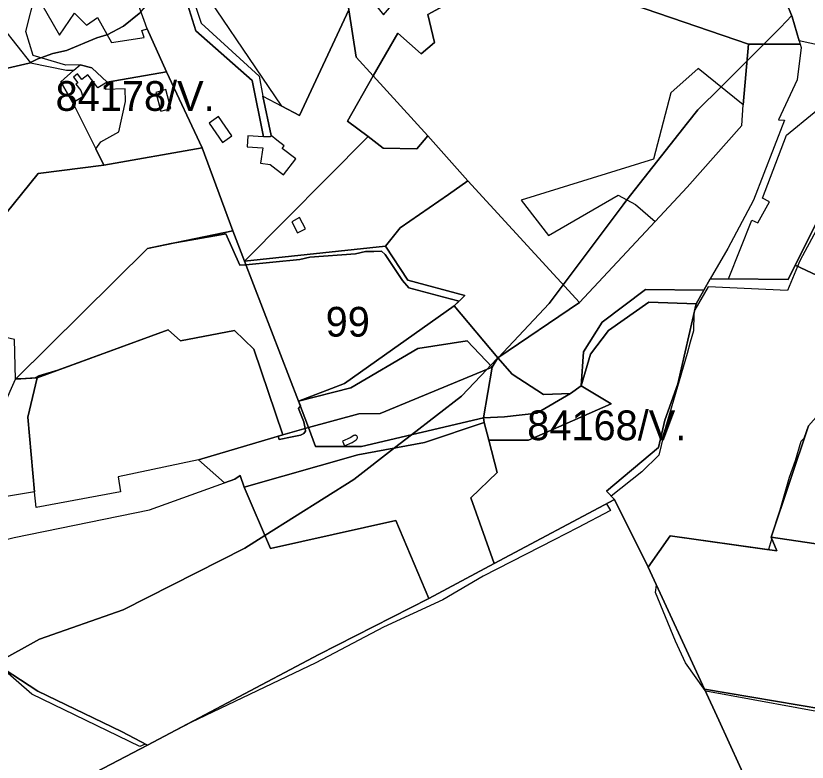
# Model space of a CAD drawing. Extents: x -477304 to -465429, y -1159113 to -1149210.
# Drawn here: x -472989.3 to -472589.9, y -1156050.1 to -1155673.5 of the extents above; entities that cross this region are included whole.
import ezdxf

# ---------------------------------------------------------------- set-up
doc = ezdxf.new("R2010")
doc.units = 0
for name, color, linetype in [('BPEJ_s', 7, 'Continuous'), ('orna_s', 7, 'Continuous'), ('PUPFL_s', 7, 'Continuous'), ('trav_porost_s', 7, 'Continuous')]:
    doc.layers.add(name, color=color, linetype=linetype)

msp = doc.modelspace()

# ---------------------------------------------------------------- linework, layer by layer
at = {"layer": 'BPEJ_s'}
for points in [[(-472922.7, -1155667.34), (-472926.21, -1155671.37), (-472927.05, -1155672.33), (-472934.92, -1155678.7), (-472943.3, -1155683.11), (-472943.42, -1155683.17), (-472948.52, -1155684.66), (-472963.83, -1155691.04), (-472970.64, -1155692.53), (-472976.73, -1155694.73), (-472977.77, -1155695.1), (-472978.3, -1155695.29), (-472982, -1155697.14), (-472982.55, -1155697.42), (-472998.16, -1155700.91)], [(-472999.06, -1156000), (-472977.35, -1155987.95), (-472935.14, -1155973.23), (-472873.79, -1155942.06), (-472863.6, -1155935.65), (-472818.82, -1155907.46), (-472798.19, -1155891.57), (-472789.56, -1155884.92), (-472764.35, -1155865.5), (-472751.49, -1155851.86), (-472749.73, -1155849.99), (-472746.1, -1155846.14), (-472746.04, -1155846.07), (-472745.98, -1155846.01), (-472720.17, -1155818.63), (-472713.13, -1155809.22), (-472682.88, -1155768.82), (-472680.95, -1155766.37), (-472650.31, -1155727.58), (-472645.08, -1155720.96), (-472633.43, -1155709.38), (-472620.23, -1155696.26), (-472611.73, -1155687.81), (-472603.37, -1155679.49), (-472597.67, -1155673.42)], [(-472597.67, -1155673.42), (-472603.37, -1155679.49), (-472611.73, -1155687.81), (-472620.23, -1155696.26), (-472633.43, -1155709.38), (-472645.08, -1155720.96), (-472650.31, -1155727.58), (-472680.95, -1155766.37), (-472682.88, -1155768.82), (-472713.13, -1155809.22), (-472720.17, -1155818.63), (-472745.98, -1155846.01), (-472746.04, -1155846.07), (-472746.1, -1155846.14), (-472749.73, -1155849.99), (-472751.49, -1155851.86), (-472764.35, -1155865.5), (-472789.56, -1155884.92), (-472798.19, -1155891.57), (-472818.82, -1155907.46), (-472863.6, -1155935.65), (-472873.79, -1155942.06), (-472935.14, -1155973.23), (-472977.35, -1155987.95), (-472999.06, -1156000)], [(-472998.16, -1155700.91), (-472982.55, -1155697.42), (-472982, -1155697.14), (-472978.3, -1155695.29), (-472977.77, -1155695.1), (-472976.73, -1155694.73), (-472970.64, -1155692.53), (-472963.83, -1155691.04), (-472948.52, -1155684.66), (-472943.42, -1155683.17), (-472943.3, -1155683.11), (-472934.92, -1155678.7), (-472927.05, -1155672.33)], [(-472585.41, -1155781.89), (-472593.44, -1155796.84), (-472594.07, -1155798.33), (-472594.75, -1155799.96), (-472599.87, -1155812.06), (-472639.86, -1155810.3), (-472646.67, -1155821.88), (-472647.11, -1155823.83), (-472647.28, -1155832.44), (-472648.94, -1155838.21), (-472650.59, -1155843.95), (-472661.52, -1155881.31), (-472664.83, -1155895.16), (-472673.42, -1155903.55), (-472688.8, -1155915.86), (-472687.19, -1155917.6), (-472691.17, -1155919.72), (-472689.22, -1155923.06), (-472705.8, -1155931.93), (-472717.7, -1155937.98), (-472753.4, -1155956.22), (-472773.89, -1155968.12), (-472803.73, -1155981.97), (-472837.9, -1156000), (-472901.01, -1156029.99), (-472922.96, -1156041.59), (-472924.1, -1156040.97), (-472926.8, -1156042.25), (-472981.23, -1156015.76), (-472997.16, -1156001.93)], [(-472585.41, -1155781.89), (-472593.44, -1155796.84), (-472594.07, -1155798.33), (-472594.75, -1155799.96), (-472599.87, -1155812.06), (-472639.86, -1155810.3), (-472646.67, -1155821.88), (-472647.11, -1155823.83), (-472647.28, -1155832.44), (-472648.94, -1155838.21), (-472650.59, -1155843.95)], [(-472650.59, -1155843.95), (-472661.52, -1155881.31), (-472664.83, -1155895.16), (-472673.42, -1155903.55), (-472688.8, -1155915.86), (-472687.19, -1155917.6), (-472691.17, -1155919.72), (-472689.22, -1155923.06), (-472705.8, -1155931.93), (-472717.7, -1155937.98), (-472753.4, -1155956.22), (-472773.89, -1155968.12), (-472803.73, -1155981.97), (-472837.9, -1156000), (-472901.01, -1156029.99), (-472922.96, -1156041.59), (-472924.1, -1156040.97), (-472926.8, -1156042.25), (-472981.23, -1156015.76), (-472997.16, -1156001.93)], [(-472571.21, -1156027.12), (-472641.15, -1156014.28), (-472641.35, -1156014.01), (-472651.43, -1156000), (-472656.44, -1155989.1), (-472666.48, -1155964.42), (-472665.94, -1155960.8), (-472670.13, -1155951.75), (-472659.11, -1155935.96), (-472609.16, -1155942.97), (-472609.23, -1155942.79), (-472609.29, -1155942.63), (-472607.77, -1155937.52), (-472608.16, -1155936.56), (-472603.52, -1155922.75), (-472598.9, -1155906.37), (-472595.84, -1155897.86), (-472592.95, -1155888.16), (-472591.41, -1155886.7), (-472589.29, -1155880.38)], [(-472571.21, -1156027.12), (-472641.15, -1156014.28), (-472641.35, -1156014.01), (-472651.43, -1156000), (-472656.44, -1155989.1), (-472666.48, -1155964.42), (-472665.94, -1155960.8), (-472670.13, -1155951.75), (-472659.11, -1155935.96), (-472609.16, -1155942.97), (-472609.23, -1155942.79), (-472609.29, -1155942.63), (-472607.77, -1155937.52), (-472608.16, -1155936.56), (-472603.52, -1155922.75), (-472598.9, -1155906.37), (-472595.84, -1155897.86), (-472592.95, -1155888.16), (-472591.41, -1155886.7), (-472589.29, -1155880.38)]]:
    msp.add_lwpolyline(points, dxfattribs=at)
for points in [[(-472883.38, -1155783.49), (-472876.34, -1155799.4), (-472873.26, -1155799.11), (-472846.03, -1155796.51), (-472840.93, -1155795.23), (-472817.96, -1155793.53), (-472812.86, -1155792.47), (-472808.73, -1155792.36), (-472804.78, -1155792.25), (-472802.87, -1155793.95), (-472794.15, -1155807.14), (-472790.96, -1155810.75), (-472773.31, -1155815.43), (-472765.65, -1155817.46), (-472768.13, -1155819.86), (-472823.5, -1155858.96), (-472846.71, -1155867.87), (-472845.74, -1155870.37), (-472846.67, -1155871.57), (-472843.91, -1155878.37), (-472843.3, -1155881.73), (-472843.06, -1155883.05), (-472843.91, -1155884.33), (-472845.61, -1155885.18), (-472849.89, -1155886), (-472856.42, -1155887.26), (-472856.97, -1155885.68), (-472854.55, -1155884.97), (-472869.3, -1155841.75), (-472879.05, -1155832.25), (-472906.29, -1155837.48), (-472912.41, -1155832.04), (-472968.11, -1155852.34), (-472977.66, -1155855.19), (-472979.6, -1155856.24), (-472986.85, -1155856.72), (-472989.11, -1155856.43), (-472922.84, -1155790.9), (-472910.99, -1155788.46), (-472886.01, -1155783.96)], [(-472883.38, -1155783.49), (-472886.01, -1155783.96), (-472910.99, -1155788.46), (-472922.84, -1155790.9), (-472989.11, -1155856.43), (-472986.85, -1155856.72), (-472979.6, -1155856.24), (-472977.66, -1155855.19), (-472968.11, -1155852.34), (-472912.41, -1155832.04), (-472906.29, -1155837.48), (-472879.05, -1155832.25), (-472869.3, -1155841.75), (-472854.55, -1155884.97), (-472856.97, -1155885.68), (-472856.42, -1155887.26), (-472849.89, -1155886), (-472845.61, -1155885.18), (-472843.91, -1155884.33), (-472843.06, -1155883.05), (-472843.3, -1155881.73), (-472843.91, -1155878.37), (-472846.67, -1155871.57), (-472845.74, -1155870.37), (-472846.71, -1155867.87), (-472823.5, -1155858.96), (-472768.13, -1155819.86), (-472765.65, -1155817.46), (-472773.31, -1155815.43), (-472790.96, -1155810.75), (-472794.15, -1155807.14), (-472802.87, -1155793.95), (-472804.78, -1155792.25), (-472808.73, -1155792.36), (-472812.86, -1155792.47), (-472817.96, -1155793.53), (-472840.93, -1155795.23), (-472846.03, -1155796.51), (-472873.26, -1155799.11), (-472876.34, -1155799.4)]]:
    msp.add_lwpolyline(points, close=True, dxfattribs=at)
at = {"layer": 'orna_s'}
msp.add_lwpolyline([(-472904.44, -1155646.21), (-472874.2, -1155639.71), (-472825.33, -1155645.43), (-472821.33, -1155670.54), (-472846.2, -1155723.83), (-472855.05, -1155719.18)], close=True, dxfattribs=at)
at = {"layer": 'PUPFL_s'}
for points in [[(-472572.16, -1155777.59), (-472514.27, -1155815.34), (-472498.14, -1155825.67), (-472490.85, -1155822.58), (-472477.53, -1155830.42), (-472448.56, -1155789.04), (-472474.55, -1155756.52), (-472484.66, -1155743.65), (-472534.93, -1155704.64), (-472531.73, -1155698.69), (-472519.37, -1155692.24), (-472415.14, -1155824.92), (-472416.46, -1155829.67), (-472432.07, -1155851.62), (-472438.54, -1155857.96), (-472472.35, -1155859.71), (-472574.19, -1155809.59), (-472596.01, -1155799.37), (-472572.9, -1155753.43), (-472551.81, -1155736.18)], [(-472841.55, -1155881.23), (-472854.55, -1155884.97), (-472869.3, -1155841.75), (-472879.05, -1155832.25), (-472906.29, -1155837.48), (-472912.41, -1155832.04), (-472978.64, -1155856.18), (-472989.58, -1155856.9), (-472922.84, -1155790.9), (-472879.9, -1155782.07), (-472873.94, -1155797.34), (-472846.71, -1155867.87)], [(-472873.94, -1155797.34), (-472802.83, -1155789.76), (-472791.56, -1155806.97), (-472762.68, -1155814.59), (-472768.13, -1155819.86), (-472823.5, -1155858.96), (-472846.71, -1155867.87)], [(-472661.79, -1155877.51), (-472655.14, -1155859.25), (-472645.98, -1155818.85), (-472642.13, -1155812), (-472638.84, -1155806.16), (-472629.58, -1155806.24), (-472599.61, -1155806.52), (-472596.01, -1155799.37), (-472574.19, -1155809.59), (-472472.35, -1155859.71), (-472488.97, -1155894.11), (-472503.35, -1155895.81), (-472532.79, -1155892.95), (-472559.66, -1155893.64), (-472569.59, -1155891.1), (-472584.19, -1155874.69), (-472589.29, -1155880.38), (-472608.16, -1155936.56), (-472605.33, -1155943.51), (-472659.11, -1155935.96), (-472670.13, -1155951.75), (-472687.19, -1155917.6), (-472691.18, -1155913.29), (-472664.95, -1155891.32)], [(-472742.74, -1155875.87), (-472753.29, -1155876.35), (-472748.95, -1155850.81), (-472746.05, -1155846.06), (-472738.91, -1155854.32), (-472723.07, -1155864.54), (-472709.44, -1155864.05), (-472726.33, -1155874.06)], [(-472748.95, -1155850.81), (-472753.29, -1155876.35), (-472814.81, -1155890.89), (-472838.13, -1155890.86), (-472841.55, -1155881.23), (-472816.2, -1155874.36), (-472805.5, -1155874.22)], [(-472704.05, -1155860.24), (-472688.81, -1155869.22), (-472730.61, -1155887.59), (-472750.54, -1155887.57), (-472752.92, -1155878.75), (-472753.29, -1155876.35), (-472742.74, -1155875.87), (-472726.33, -1155874.06), (-472709.44, -1155864.05)], [(-472841.55, -1155881.23), (-472838.13, -1155890.86), (-472814.81, -1155890.89), (-472753.29, -1155876.35), (-472752.92, -1155878.75), (-472783.15, -1155888.77), (-472816.72, -1155895.02), (-472874.07, -1155911.28), (-472876.19, -1155905.49), (-472878.88, -1155907.3), (-472884.02, -1155909.16), (-472897.09, -1155897.5), (-472854.55, -1155884.97)], [(-472818.77, -1155885.32), (-472820.65, -1155886.43), (-472824.44, -1155888.07), (-472823.42, -1155890.41), (-472819.64, -1155888.78), (-472817.49, -1155887.4), (-472817.37, -1155887.29), (-472817.18, -1155887.08), (-472817.04, -1155886.83), (-472816.96, -1155886.53), (-472816.95, -1155886.37), (-472816.98, -1155886.09), (-472817.1, -1155885.77), (-472817.29, -1155885.52), (-472817.53, -1155885.33), (-472817.78, -1155885.21), (-472817.97, -1155885.17), (-472818.25, -1155885.16), (-472818.53, -1155885.21)], [(-473111.65, -1156073.71), (-473056.5, -1156049.27), (-473048.89, -1156045.89), (-473050.49, -1156023.91), (-473057.72, -1156010.51), (-473038.71, -1156011.58), (-473037.79, -1155982.27), (-473034.32, -1155981.8), (-473010.5, -1156006.64), (-472999.71, -1156000.27), (-472978.22, -1156014.28), (-472935.93, -1156034.53), (-472922.96, -1156041.59), (-473045.7, -1156105.54), (-473097.04, -1156103.37), (-473101, -1156113.09), (-473145.64, -1156142.47), (-473152.6, -1156129.97), (-473153.83, -1156074.08), (-473144.15, -1156046.2), (-473122.88, -1156061.84), (-473122.25, -1156069.17)], [(-472634.3, -1156085.9), (-472613.74, -1156074.61), (-472634.46, -1156028.9), (-472641.69, -1156013.27), (-472582.01, -1156023.28), (-472562.66, -1156023.79), (-472541.93, -1156016.78), (-472537.65, -1156016.92), (-472541.68, -1156019.13), (-472538.91, -1156069.82), (-472596.62, -1156079.6)]]:
    msp.add_lwpolyline(points, close=True, dxfattribs=at)
msp.add_lwpolyline([(-473100.49, -1156468.81), (-473078.33, -1156321.91), (-473045.7, -1156105.54), (-472922.96, -1156041.59), (-472836.38, -1155995.84), (-472780.83, -1155967.48), (-472747.87, -1155949.92), (-472687.19, -1155917.6), (-472670.13, -1155951.75), (-472641.69, -1156013.27), (-472634.46, -1156028.9), (-472613.74, -1156074.61), (-472634.3, -1156085.9), (-472850.56, -1156204.67), (-472863.16, -1156211.61), (-472899.78, -1156412.46), (-472686.97, -1156467.54)], dxfattribs=at)
at = {"layer": 'trav_porost_s'}
for points in [[(-472825.33, -1155645.43), (-472816.82, -1155656.3), (-472803.73, -1155673.01), (-472788.76, -1155655.34), (-472782.65, -1155648.13), (-472797.55, -1155628.71), (-472825.33, -1155645.43), (-472834.02, -1155597.18), (-472718.7, -1155588.71), (-472701.9, -1155614.11), (-472701.84, -1155632.24), (-472739.24, -1155627.74), (-472738.35, -1155648.61), (-472727, -1155652.3), (-472740.79, -1155654.51), (-472740.31, -1155657.81), (-472765.97, -1155664.23), (-472781.32, -1155672.86), (-472778.1, -1155687.01), (-472784.81, -1155692.77), (-472796.52, -1155682.3), (-472809.03, -1155703.76), (-472817.54, -1155694.41), (-472821.33, -1155670.54)], [(-472938.48, -1155637.04), (-472939.51, -1155629.75), (-472916.76, -1155614.14), (-472914.52, -1155632.41), (-472904.62, -1155650.72), (-472895.84, -1155677.28), (-472866.51, -1155703.99), (-472864.63, -1155714.13), (-472860.5, -1155733.98), (-472860.99, -1155734.61), (-472864.32, -1155734.51), (-472870.03, -1155706.22), (-472898.52, -1155681.15), (-472907.7, -1155651.3), (-472920.94, -1155636.86)], [(-472672.2, -1155632.87), (-472629.35, -1155623.11), (-472617.53, -1155624.42), (-472597.43, -1155674), (-472593.93, -1155686.1), (-472593.45, -1155687.75), (-472619.47, -1155687.83), (-472671.7, -1155670), (-472727, -1155652.3), (-472738.35, -1155648.61), (-472739.24, -1155627.74), (-472701.84, -1155632.24)], [(-472685.36, -1155764.03), (-472676.59, -1155768.69), (-472666.59, -1155777.31), (-472704.85, -1155818.24), (-472761.29, -1155756.77), (-472781.48, -1155734.03), (-472809.03, -1155703.76), (-472796.52, -1155682.3), (-472784.81, -1155692.77), (-472778.1, -1155687.01), (-472781.32, -1155672.86), (-472765.97, -1155664.23), (-472740.31, -1155657.81), (-472740.79, -1155654.51), (-472727, -1155652.3), (-472671.7, -1155670), (-472619.47, -1155687.83), (-472622.25, -1155718.47), (-472644.89, -1155700.06), (-472658.74, -1155712.37), (-472667.58, -1155745.86), (-472734.29, -1155766.5), (-472720.46, -1155784.36)], [(-472959.66, -1155672.24), (-472953.72, -1155678.23), (-472948.17, -1155674.4), (-472941.08, -1155687.07), (-472924.64, -1155684.52), (-472925.74, -1155681.01), (-472923.11, -1155680.05), (-472913.24, -1155701.82), (-472943.29, -1155707.06), (-472951.01, -1155699.76), (-472956.94, -1155698.28), (-472964.13, -1155698.43), (-472980.61, -1155693.59), (-472984.29, -1155681.38), (-472979.36, -1155662.17), (-472967.33, -1155683.31)], [(-472998.55, -1155704.27), (-472995.67, -1155679.73), (-472981.91, -1155697.25), (-472963.84, -1155700.94), (-472960.02, -1155700.99), (-472966.66, -1155706.82), (-472960.52, -1155717.37), (-472949.03, -1155740.56), (-472944.94, -1155748.81), (-472978.04, -1155753.06), (-472998.57, -1155778.3), (-473002.71, -1155739.02), (-473042.47, -1155744.26), (-473043.29, -1155736.01), (-473043.13, -1155717.33), (-473006.44, -1155706.58)], [(-472622.99, -1155728.81), (-472622.25, -1155718.47), (-472619.47, -1155687.83), (-472593.45, -1155687.75), (-472592.97, -1155689.43), (-472595, -1155705.79), (-472604.46, -1155725.98), (-472601.32, -1155726.25), (-472617.01, -1155766.52), (-472629.97, -1155790.89), (-472638.84, -1155806.16), (-472642.13, -1155812), (-472671.49, -1155811.6), (-472693.44, -1155828.03), (-472702.86, -1155843.1), (-472704.05, -1155860.24), (-472709.44, -1155864.05), (-472723.07, -1155864.54), (-472738.91, -1155854.32), (-472746.05, -1155846.06), (-472704.85, -1155818.24), (-472666.59, -1155777.31), (-472650.57, -1155760.02)], [(-472950.53, -1155706.49), (-472952.99, -1155703.33), (-472955.99, -1155705.67), (-472958.18, -1155702.87), (-472960.23, -1155704.47), (-472958.05, -1155707.27), (-472959.07, -1155708.07), (-472956.61, -1155711.23), (-472955.55, -1155714.39), (-472960.52, -1155717.37), (-472966.66, -1155706.82), (-472960.02, -1155700.99), (-472956.94, -1155698.28), (-472951.01, -1155699.76), (-472943.29, -1155707.06), (-472947.93, -1155709.83)], [(-472946.51, -1155737.07), (-472937.33, -1155731.99), (-472934.01, -1155716.68), (-472934.22, -1155710.42), (-472944.02, -1155710.75), (-472943.29, -1155707.06), (-472913.24, -1155701.82), (-472895.22, -1155740.09), (-472944.94, -1155748.81), (-472949.03, -1155740.56)], [(-472809.03, -1155703.76), (-472781.48, -1155734.03), (-472786.97, -1155740.59), (-472804, -1155740.25), (-472811.58, -1155734.37), (-472821.93, -1155726.6)], [(-472911.03, -1155720.31), (-472913.56, -1155710.73), (-472918.75, -1155712.16), (-472916.14, -1155721.66)], [(-472885.03, -1155737.43), (-472880.24, -1155734.09), (-472887.03, -1155724.32), (-472891.83, -1155727.66)], [(-472802.83, -1155789.76), (-472873.94, -1155797.34), (-472811.58, -1155734.37), (-472804, -1155740.25), (-472786.97, -1155740.59), (-472781.48, -1155734.03), (-472761.29, -1155756.77), (-472770.95, -1155763.7), (-472795.33, -1155780.53)], [(-472998.57, -1155778.3), (-472978.04, -1155753.06), (-472944.94, -1155748.81), (-472895.22, -1155740.09), (-472879.9, -1155782.07), (-472922.84, -1155790.9), (-472989.58, -1155856.9), (-472990.03, -1155836.86), (-473006.77, -1155833.03), (-473033.2, -1155864.05), (-473051.45, -1155878.73), (-473066.44, -1155882.55), (-473077.38, -1155876.66), (-473078.66, -1155852.71), (-473071.89, -1155844.14), (-473055.44, -1155848.25)], [(-472802.83, -1155789.76), (-472795.33, -1155780.53), (-472770.95, -1155763.7), (-472761.29, -1155756.77), (-472704.85, -1155818.24), (-472746.05, -1155846.06), (-472768.13, -1155819.86), (-472762.68, -1155814.59), (-472791.56, -1155806.97)], [(-472846.18, -1155775.33), (-472850.1, -1155777.42), (-472847.12, -1155783.02), (-472843.19, -1155780.93)], [(-472669.89, -1155817.96), (-472690.14, -1155832.27), (-472699.38, -1155844.24), (-472704.05, -1155860.24), (-472702.86, -1155843.1), (-472693.44, -1155828.03), (-472671.49, -1155811.6), (-472642.13, -1155812), (-472645.98, -1155818.85)], [(-472820.21, -1155861.18), (-472846.71, -1155867.87), (-472823.5, -1155858.96), (-472768.13, -1155819.86), (-472746.05, -1155846.06), (-472748.95, -1155850.81), (-472761.62, -1155837.59), (-472786.52, -1155841.45)], [(-472688.81, -1155869.22), (-472704.05, -1155860.24), (-472699.38, -1155844.24), (-472690.14, -1155832.27), (-472669.89, -1155817.96), (-472645.98, -1155818.85), (-472655.14, -1155859.25), (-472661.79, -1155877.51), (-472664.95, -1155891.32), (-472691.18, -1155913.29), (-472687.19, -1155917.6), (-472747.87, -1155949.92), (-472759.73, -1155916.8), (-472746.36, -1155903.9), (-472750.54, -1155887.57), (-472730.61, -1155887.59)], [(-472854.55, -1155884.97), (-472897.09, -1155897.5), (-472937.7, -1155906.16), (-472936.55, -1155913.61), (-472979.1, -1155921.62), (-472979.96, -1155913.61), (-472983.34, -1155875.95), (-472978.64, -1155856.18), (-472912.41, -1155832.04), (-472906.29, -1155837.48), (-472879.05, -1155832.25), (-472869.3, -1155841.75)], [(-472786.52, -1155841.45), (-472761.62, -1155837.59), (-472748.95, -1155850.81), (-472805.5, -1155874.22), (-472816.2, -1155874.36), (-472841.55, -1155881.23), (-472846.71, -1155867.87), (-472820.21, -1155861.18)], [(-472989.58, -1155856.9), (-472978.64, -1155856.18), (-472983.34, -1155875.95), (-472979.96, -1155913.61), (-473008.24, -1155918.43), (-473007.96, -1155898.21)], [(-472522.82, -1155939.69), (-472550.24, -1155943.48), (-472550.23, -1155945.13), (-472608.16, -1155936.56), (-472589.29, -1155880.38), (-472584.19, -1155874.69), (-472569.59, -1155891.1), (-472559.66, -1155893.64), (-472532.79, -1155892.95), (-472503.35, -1155895.81), (-472488.97, -1155894.11), (-472480.63, -1155893.13), (-472466.99, -1155889.19), (-472469.78, -1155915.52), (-472493, -1155921.91), (-472510.3, -1155931.11)], [(-472759.73, -1155916.8), (-472747.87, -1155949.92), (-472780.83, -1155967.48), (-472797.52, -1155928.1), (-472860.75, -1155942.28), (-472874.07, -1155911.28), (-472816.72, -1155895.02), (-472783.15, -1155888.77), (-472752.92, -1155878.75), (-472750.54, -1155887.57), (-472746.36, -1155903.9)], [(-472860.75, -1155942.28), (-472797.52, -1155928.1), (-472780.83, -1155967.48), (-472836.38, -1155995.84), (-472922.96, -1156041.59), (-472935.93, -1156034.53), (-472978.22, -1156014.28), (-472999.71, -1156000.27), (-473010.5, -1156006.64), (-473034.32, -1155981.8), (-473037.79, -1155982.27), (-473041.49, -1155979.65), (-473057.24, -1155953.81), (-473055.09, -1155953.26), (-472990.19, -1155936.77), (-472921.8, -1155922.81), (-472884.02, -1155909.16), (-472878.88, -1155907.3), (-472876.19, -1155905.49), (-472874.07, -1155911.28)], [(-472537.65, -1156016.92), (-472541.93, -1156016.78), (-472562.66, -1156023.79), (-472582.01, -1156023.28), (-472641.69, -1156013.27), (-472670.13, -1155951.75), (-472659.11, -1155935.96), (-472605.33, -1155943.51), (-472608.16, -1155936.56), (-472550.23, -1155945.13), (-472550.19, -1155950.13), (-472537.25, -1155947.44), (-472504.06, -1155998.51)]]:
    msp.add_lwpolyline(points, close=True, dxfattribs=at)
for points in [[(-472485.43, -1155637.29), (-472498.78, -1155673.99), (-472515, -1155689.94), (-472519.37, -1155692.24), (-472531.73, -1155698.69), (-472534.93, -1155704.64), (-472551.81, -1155736.18), (-472572.9, -1155753.43), (-472596.01, -1155799.37), (-472599.61, -1155806.52), (-472629.58, -1155806.24), (-472617.92, -1155776.64), (-472614.83, -1155777.91), (-472608.88, -1155767.38), (-472612.41, -1155765.56), (-472600.29, -1155733.82), (-472572.48, -1155710.8), (-472565.63, -1155692.3), (-472593.93, -1155686.1), (-472597.43, -1155674), (-472617.53, -1155624.42)], [(-472907.7, -1155651.3), (-472898.52, -1155681.15), (-472870.03, -1155706.22), (-472864.32, -1155734.51), (-472872.26, -1155734.12), (-472872.53, -1155739.71), (-472864.6, -1155740.1), (-472865.87, -1155747.79), (-472861.03, -1155748.55), (-472854.26, -1155753.71), (-472848.09, -1155745.62), (-472854.86, -1155740.46), (-472853.89, -1155739.18), (-472857.54, -1155736.3), (-472860.5, -1155733.98), (-472864.63, -1155714.13), (-472855.05, -1155719.18), (-472846.2, -1155723.83), (-472821.33, -1155670.54), (-472817.54, -1155694.41), (-472809.03, -1155703.76), (-472821.93, -1155726.6), (-472811.58, -1155734.37), (-472873.94, -1155797.34), (-472879.9, -1155782.07), (-472895.22, -1155740.09), (-472913.24, -1155701.82), (-472923.11, -1155680.05), (-472938.48, -1155637.04)]]:
    msp.add_lwpolyline(points, dxfattribs=at)

# ---------------------------------------------------------------- texts
at = {"layer": 'BPEJ_s'}
for s, p in [('84178/V.', (-472969.28, -1155721.48)), ('99', (-472832.97, -1155835.38)), ('84168/V.', (-472731.24, -1155887.64))]:
    msp.add_text(s, height=15, dxfattribs=at).set_placement(p)

doc.saveas('drawing.dxf')
